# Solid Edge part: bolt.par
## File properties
Author: Deepak Maini
Template: Normal.par
Last saved by: Robert a Rhodes jr
Revision: 3
Application: Solid Edge
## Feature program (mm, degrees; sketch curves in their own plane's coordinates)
sketch for "unnamed RevolvedProtrusion 1" plane through (0, 0, 0) normal (0, -1, 0) x-axis (1, 0, 0)
  line (0, 40.7664) -> (14.7729, 40.7664)
  line (14.7729, 40.7664) -> (14.7729, 29.2752)
  line (14.7729, 29.2752) -> (8.0228, 29.2752)
  line (8.0228, 29.2752) -> (8.0228, -6.0192)
  line (8.0228, -6.0192) -> (0, -6.0192)
  line (0, -6.0192) -> (0, 40.7664)
revolve "unnamed RevolvedProtrusion 1" add full turn 360 deg
sketch for "unnamed Cutout 1" plane through (0, 0, 40.7664) normal (0, 0, 1) x-axis (1, 0, 0)
  line (-7.0309, 0) -> (-3.9268, 6.0697)
  line (-3.9268, 6.0697) -> (3.076, 6.0697)
  line (3.076, 6.0697) -> (7.0309, 0)
  line (7.0309, 0) -> (3.2724, -6.223)
  line (3.2724, -6.223) -> (-3.2724, -6.223)
  line (-3.2724, -6.223) -> (-7.0309, 0)
extrude "unnamed Cutout 1" cut finite 6.35 along -normal
chamfer "unnamed Chamfer 1"
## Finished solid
Body 1: solid body, 13 faces, 23 edges, 12 vertices.
  Faces by surface: plane 10, cylinder 2, cone 1
  Edges by curve: line 18, circle 5
Bounding box of the edges (mm): 29.546 x 29.546 x 46.786, from (-14.7729, -14.7729, -6.0192) to (14.7729, 14.7729, 40.7664).
Cylindrical faces by radius (mm): R8.0228 x1, R14.7729 x1
Conical faces (half-angle, radius in mm at the cone's reference point): 45 deg R12.7729 x1
Planar faces by outward normal: +y 1, +z 2, -y 1, -z 2, oblique 4
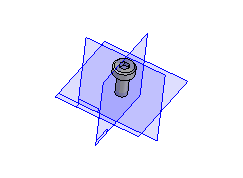
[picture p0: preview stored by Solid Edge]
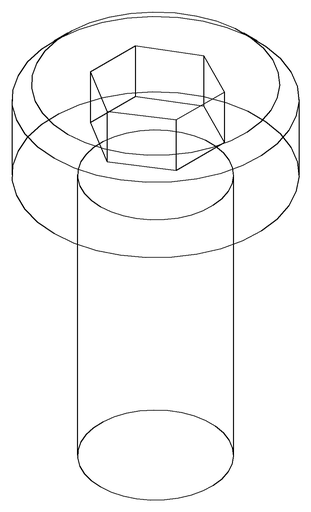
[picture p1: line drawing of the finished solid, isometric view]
